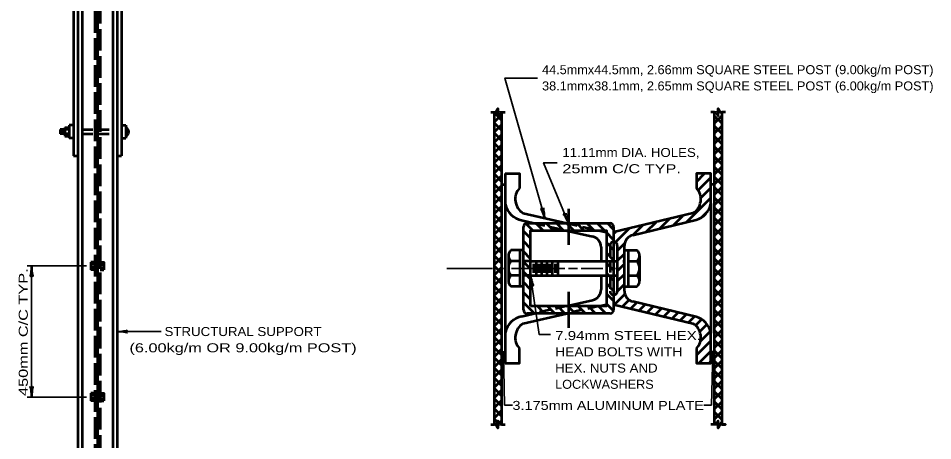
# Model space of a CAD drawing. Extents: x -96 to 759, y -450 to 94.
# Drawn here: x 216.3 to 520.4, y -261.3 to -120.9 of the extents above; entities that cross this region are included whole.
import ezdxf
from ezdxf.enums import TextEntityAlignment as Align

# ---------------------------------------------------------------- set-up
doc = ezdxf.new("R2010")
doc.units = 0
doc.header["$LTSCALE"] = 1.2
doc.linetypes.add('LONG_DASHED', pattern=[7.5, 6, -1.5])
doc.linetypes.add('MEDIUM_DASHED', pattern=[4.5, 3, -1.5])
doc.layers.add('1', color=7, linetype='Continuous', lineweight=53)

msp = doc.modelspace()

# ---------------------------------------------------------------- linework, layer by layer
at = {"layer": '1'}
for p, q in [((237.567, -31.518), (237.567, -274.002)), ((242.649, -31.518), (242.649, -266.742)), ((234.663, -34.422), (234.663, -166.554)), ((236.115, -34.422), (236.115, -274.002)), ((247.731, -34.422), (247.731, -274.002)), ((249.183, -34.422), (249.183, -274.002)), ((250.635, -34.422), (250.635, -166.554)), ((449.028, -151.1), (449.096, -151.032)), ((449.311, -151.461), (449.028, -151.179)), ((373.428, -152.096), (374.628, -152.096)), ((377.028, -154.717), (374.628, -152.317)), ((374.628, -155.254), (377.028, -152.854)), ((377.028, -152.096), (378.228, -152.096)), ((447.828, -152.096), (446.628, -152.096)), ((447.828, -152.3), (448.032, -152.096)), ((447.828, -155.694), (450.228, -153.294)), ((450.228, -155.773), (447.828, -153.373)), ((450.228, -152.379), (449.945, -152.096)), ((451.428, -152.096), (450.228, -152.096)), ((233.211, -157.842), (230.307, -157.842)), ((230.307, -157.842), (230.307, -159.294)), ((231.759, -157.116), (231.759, -160.02)), ((231.759, -157.116), (233.211, -157.116)), ((234.663, -156.39), (233.211, -156.39)), ((233.211, -156.39), (233.211, -160.746)), ((250.635, -156.39), (252.087, -156.39)), ((252.087, -156.39), (252.087, -160.746)), ((377.028, -158.111), (374.628, -155.711)), ((374.628, -158.648), (377.028, -156.248)), ((447.828, -159.088), (450.228, -156.688)), ((450.228, -159.167), (447.828, -156.767)), ((233.211, -159.294), (230.307, -159.294)), ((231.033, -158.205), (231.033, -158.931)), ((231.759, -160.02), (233.211, -160.02)), ((234.663, -160.746), (233.211, -160.746)), ((250.635, -160.746), (252.087, -160.746)), ((377.028, -161.505), (374.628, -159.105)), ((374.628, -162.042), (377.028, -159.642)), ((447.828, -162.482), (450.228, -160.082)), ((450.228, -162.561), (447.828, -160.161)), ((377.028, -164.899), (374.628, -162.499)), ((374.628, -165.436), (377.028, -163.036)), ((447.828, -165.876), (450.228, -163.476)), ((450.228, -165.955), (447.828, -163.555)), ((234.663, -166.554), (236.115, -166.554)), ((249.183, -166.554), (250.635, -166.554)), ((377.028, -168.293), (374.628, -165.894)), ((374.628, -168.83), (377.028, -166.43)), ((447.828, -169.27), (450.228, -166.871)), ((450.228, -169.349), (447.828, -166.949)), ((377.028, -171.688), (374.628, -169.288)), ((374.628, -172.224), (377.028, -169.824)), ((377.028, -175.082), (374.628, -172.682)), ((374.628, -175.619), (377.028, -173.219)), ((378.228, -172.496), (378.228, -235.496)), ((441.828, -175.188), (444.52, -172.496)), ((447.828, -172.665), (450.228, -170.265)), ((450.228, -172.743), (447.828, -170.343)), ((377.028, -178.476), (374.628, -176.076)), ((377.028, -176.096), (378.228, -176.096)), ((442.385, -178.025), (446.628, -173.782)), ((447.828, -176.096), (446.628, -176.096)), ((447.828, -176.059), (450.228, -173.659)), ((450.228, -176.137), (447.828, -173.737)), ((374.628, -179.013), (377.028, -176.613)), ((443.239, -180.565), (446.628, -177.176)), ((447.828, -179.453), (450.228, -177.053)), ((450.228, -179.532), (447.828, -177.132)), ((377.028, -181.87), (374.628, -179.47)), ((374.628, -182.407), (377.028, -180.007)), ((438.535, -188.663), (446.628, -180.57)), ((447.828, -182.847), (450.228, -180.447)), ((450.228, -182.926), (447.828, -180.526)), ((377.028, -185.264), (374.628, -182.864)), ((374.628, -185.801), (377.028, -183.401)), ((399.296, -184.184), (399.296, -196.184)), ((399.296, -184.184), (399.296, -196.184)), ((443.512, -187.08), (445.634, -184.958)), ((446.628, -182.454), (446.628, -225.537)), ((447.828, -186.241), (450.228, -183.841)), ((450.228, -186.32), (447.828, -183.92)), ((377.028, -188.658), (374.628, -186.258)), ((374.628, -189.195), (377.028, -186.795)), ((383.696, -188.036), (387.866, -188.984)), ((384.228, -185.696), (398.696, -188.984)), ((420.66, -192.932), (441.707, -187.906)), ((429.617, -190.793), (432.858, -187.551)), ((434.076, -189.728), (437.317, -186.486)), ((447.828, -189.635), (450.228, -187.235)), ((450.228, -189.714), (447.828, -187.314)), ((377.028, -192.052), (374.628, -189.652)), ((374.628, -192.589), (377.028, -190.189)), ((384.296, -217.808), (384.296, -190.184)), ((387.454, -191.384), (385.124, -189.053)), ((385.496, -188.984), (413.096, -188.984)), ((390.848, -191.384), (388.448, -188.984)), ((394.243, -191.384), (391.843, -188.984)), ((397.637, -191.384), (395.237, -188.984)), ((398.426, -191.384), (407.294, -193.399)), ((401.031, -191.384), (398.631, -188.984)), ((404.425, -191.384), (402.025, -188.984)), ((407.819, -191.384), (405.419, -188.984)), ((411.213, -191.384), (408.813, -188.984)), ((409.256, -191.384), (411.896, -191.984)), ((414.296, -191.073), (412.207, -188.984)), ((414.296, -190.184), (414.296, -191.984)), ((414.902, -195.325), (419.482, -190.746)), ((420.699, -192.922), (423.941, -189.681)), ((425.158, -191.858), (428.399, -188.616)), ((447.828, -193.029), (450.228, -190.629)), ((450.228, -193.108), (447.828, -190.708)), ((377.028, -195.446), (374.628, -193.046)), ((374.628, -195.983), (377.028, -193.583)), ((386.696, -194.02), (384.296, -191.62)), ((414.296, -194.467), (411.896, -192.067)), ((414.296, -192.537), (415.023, -191.81)), ((447.828, -196.423), (450.228, -194.023)), ((450.228, -196.502), (447.828, -194.102)), ((377.028, -198.841), (374.628, -196.441)), ((374.628, -199.377), (377.028, -196.977)), ((386.696, -197.414), (384.296, -195.014)), ((410.096, -196.91), (410.096, -201.596)), ((414.296, -197.861), (411.896, -195.461)), ((414.296, -195.134), (414.296, -212.858)), ((415.496, -198.126), (417.989, -195.633)), ((415.496, -196.433), (415.496, -211.558)), ((417.896, -211.558), (417.896, -196.433)), ((447.828, -199.817), (450.228, -197.418)), ((450.228, -199.896), (447.828, -197.496)), ((377.028, -202.235), (374.628, -199.835)), ((374.628, -202.771), (377.028, -200.371)), ((379.288, -199.802), (379.288, -208.189)), ((384.296, -197.996), (380.096, -197.996)), ((383.096, -197.996), (383.096, -209.996)), ((386.696, -200.808), (384.296, -198.408)), ((414.296, -201.255), (411.896, -198.855)), ((415.496, -201.52), (417.896, -199.12)), ((417.896, -197.996), (422.096, -197.996)), ((419.096, -197.996), (419.096, -209.996)), ((422.903, -199.802), (422.903, -208.189)), ((240.471, -201.947), (240.471, -204.488)), ((241.742, -201.947), (240.471, -201.947)), ((377.028, -205.629), (374.628, -203.229)), ((383.096, -201.596), (380.096, -201.596)), ((386.696, -204.202), (384.296, -201.802)), ((386.696, -201.596), (411.896, -201.596)), ((387.596, -202.496), (387.596, -205.496)), ((388.496, -201.596), (388.496, -206.396)), ((389.396, -202.496), (389.396, -205.496)), ((390.296, -201.596), (390.296, -206.396)), ((391.196, -202.496), (391.196, -205.496)), ((392.096, -201.596), (392.096, -206.396)), ((392.996, -202.496), (392.996, -205.496)), ((393.896, -201.596), (393.896, -206.396)), ((394.796, -202.496), (394.796, -205.496)), ((395.696, -201.596), (395.696, -206.396)), ((414.296, -204.649), (411.896, -202.249)), ((415.496, -204.914), (417.896, -202.514)), ((419.096, -201.596), (422.096, -201.596)), ((447.828, -203.212), (450.228, -200.812)), ((450.228, -203.29), (447.828, -200.89)), ((241.742, -204.488), (240.471, -204.488)), ((243.557, -204.488), (244.827, -204.488)), ((374.628, -206.166), (377.028, -203.766)), ((377.028, -209.023), (374.628, -206.623)), ((383.096, -206.396), (380.096, -206.396)), ((386.696, -207.596), (384.296, -205.196)), ((386.696, -206.396), (411.896, -206.396)), ((410.096, -206.396), (410.096, -211.082)), ((414.296, -208.043), (411.896, -205.643)), ((415.496, -208.308), (417.896, -205.908)), ((419.096, -206.396), (422.096, -206.396)), ((447.828, -206.606), (450.228, -204.206)), ((450.228, -206.684), (447.828, -204.284)), ((374.628, -209.56), (377.028, -207.16)), ((386.696, -210.99), (384.296, -208.59)), ((414.296, -211.437), (411.896, -209.037)), ((415.475, -211.723), (417.896, -209.302)), ((447.828, -210), (450.228, -207.6)), ((450.228, -210.079), (447.828, -207.679)), ((377.028, -212.417), (374.628, -210.017)), ((374.628, -212.954), (377.028, -210.554)), ((384.296, -209.996), (380.096, -209.996)), ((386.696, -214.384), (384.296, -211.984)), ((399.296, -211.808), (399.296, -223.808)), ((399.296, -211.808), (399.296, -223.808)), ((414.296, -214.831), (411.896, -212.431)), ((414.529, -216.063), (418.055, -212.536)), ((417.896, -209.996), (422.096, -209.996)), ((447.828, -213.394), (450.228, -210.994)), ((450.228, -213.473), (447.828, -211.073)), ((377.028, -215.811), (374.628, -213.411)), ((374.628, -216.348), (377.028, -213.948)), ((387.925, -219.008), (384.296, -215.378)), ((398.427, -216.608), (407.294, -214.592)), ((414.225, -218.155), (411.896, -215.826)), ((414.296, -212.902), (414.341, -212.856)), ((417.269, -216.718), (419.476, -214.51)), ((420.008, -217.372), (422, -215.38)), ((441.707, -220.086), (420.66, -215.06)), ((447.828, -216.788), (450.228, -214.388)), ((450.228, -216.867), (447.828, -214.467)), ((377.028, -219.205), (374.628, -216.805)), ((374.628, -219.742), (377.028, -217.342)), ((391.319, -219.008), (388.919, -216.608)), ((394.713, -219.008), (392.313, -216.608)), ((398.107, -219.008), (395.707, -216.608)), ((401.502, -219.008), (399.102, -216.608)), ((404.896, -219.008), (402.496, -216.608)), ((408.29, -219.008), (405.89, -216.608)), ((409.256, -216.608), (411.896, -216.008)), ((411.684, -219.008), (409.284, -216.608)), ((414.296, -216.008), (414.296, -217.808)), ((422.748, -218.026), (424.74, -216.034)), ((425.488, -218.68), (427.48, -216.689)), ((428.228, -219.335), (430.22, -217.343)), ((430.968, -219.989), (432.96, -217.997)), ((433.707, -220.643), (435.699, -218.651)), ((447.828, -220.182), (450.228, -217.782)), ((450.228, -220.261), (447.828, -217.861)), ((377.028, -222.599), (374.628, -220.199)), ((374.628, -223.136), (377.028, -220.736)), ((383.696, -219.955), (387.866, -219.008)), ((384.228, -222.296), (398.696, -219.008)), ((413.096, -219.008), (385.496, -219.008)), ((436.447, -221.298), (438.439, -219.306)), ((439.187, -221.952), (441.179, -219.96)), ((441.538, -222.995), (443.587, -220.946)), ((447.828, -223.576), (450.228, -221.176)), ((450.228, -223.655), (447.828, -221.255)), ((377.028, -225.993), (374.628, -223.593)), ((374.628, -226.53), (377.028, -224.13)), ((442.895, -225.032), (445.337, -222.59)), ((443.123, -228.198), (446.453, -224.869)), ((447.828, -226.97), (450.228, -224.57)), ((450.228, -227.049), (447.828, -224.649)), ((377.028, -229.388), (374.628, -226.988)), ((374.628, -229.924), (377.028, -227.524)), ((447.828, -230.365), (450.228, -227.965)), ((377.028, -232.782), (374.628, -230.382)), ((374.628, -233.318), (377.028, -230.918)), ((441.828, -232.888), (446.628, -228.088)), ((450.228, -230.443), (447.828, -228.043)), ((377.028, -236.176), (374.628, -233.776)), ((377.028, -231.896), (378.228, -231.896)), ((442.614, -235.496), (446.628, -231.482)), ((447.828, -231.896), (446.628, -231.896)), ((447.828, -233.759), (450.228, -231.359)), ((450.228, -233.837), (447.828, -231.437)), ((374.628, -236.713), (377.028, -234.312)), ((446.008, -235.496), (446.628, -234.876)), ((447.828, -237.153), (450.228, -234.753)), ((450.228, -237.231), (447.828, -234.831)), ((377.028, -239.57), (374.628, -237.17)), ((374.628, -240.107), (377.028, -237.707)), ((447.828, -240.547), (450.228, -238.147)), ((450.228, -240.626), (447.828, -238.226)), ((377.028, -242.964), (374.628, -240.564)), ((374.628, -243.501), (377.028, -241.101)), ((447.828, -243.941), (450.228, -241.541)), ((450.228, -244.02), (447.828, -241.62)), ((240.471, -245.507), (240.471, -248.048)), ((241.742, -245.507), (240.471, -245.507)), ((377.028, -246.358), (374.628, -243.958)), ((374.628, -246.895), (377.028, -244.495)), ((447.828, -247.335), (450.228, -244.935)), ((450.228, -247.414), (447.828, -245.014)), ((241.742, -248.048), (240.471, -248.048)), ((243.557, -248.048), (244.827, -248.048)), ((377.028, -249.752), (374.628, -247.352)), ((374.628, -250.289), (377.028, -247.889)), ((447.828, -250.729), (450.228, -248.329)), ((450.228, -250.808), (447.828, -248.408)), ((377.028, -253.146), (374.628, -250.746)), ((374.628, -253.683), (377.028, -251.283)), ((447.828, -254.123), (450.228, -251.723)), ((450.228, -254.202), (447.828, -251.802)), ((375.828, -255.34), (374.628, -254.14)), ((376.221, -255.483), (377.028, -254.677)), ((448.527, -255.896), (447.828, -255.196)), ((449.449, -255.896), (450.228, -255.117)), ((373.428, -255.896), (374.628, -255.896)), ((375.422, -256.283), (375.828, -255.877)), ((377.028, -255.896), (378.228, -255.896)), ((447.828, -255.896), (446.628, -255.896))]:
    msp.add_line(p, q, dxfattribs=at)
at = {"layer": '1', "linetype": 'LONG_DASHED'}
for p, q in [((243.557, -34.422), (243.557, -274.002)), ((241.742, -55.476), (241.742, -268.711))]:
    msp.add_line(p, q, dxfattribs=at)
at = {"layer": '1', "linetype": 'MEDIUM_DASHED'}
for p, q in [((237.567, -157.842), (247.731, -157.842)), ((237.567, -159.294), (247.731, -159.294)), ((387.866, -188.984), (398.426, -191.384)), ((398.696, -188.984), (409.256, -191.384)), ((413.096, -196.433), (413.096, -211.558)), ((241.742, -202.673), (240.471, -202.673)), ((241.742, -202.673), (243.557, -202.673)), ((241.742, -202.673), (243.557, -202.673)), ((243.557, -202.673), (244.827, -202.673)), ((386.696, -201.596), (384.296, -201.596)), ((411.896, -201.596), (417.896, -201.596)), ((241.742, -203.762), (240.471, -203.762)), ((241.742, -203.762), (243.557, -203.762)), ((243.557, -203.762), (244.827, -203.762)), ((386.696, -206.396), (384.296, -206.396)), ((411.896, -206.396), (417.896, -206.396)), ((398.427, -216.608), (387.866, -219.008)), ((409.256, -216.608), (398.696, -219.008)), ((241.742, -246.233), (240.471, -246.233)), ((241.742, -246.233), (243.557, -246.233)), ((243.557, -246.233), (244.827, -246.233)), ((241.742, -247.322), (240.471, -247.322)), ((241.742, -247.322), (243.557, -247.322)), ((243.557, -247.322), (244.827, -247.322))]:
    msp.add_line(p, q, dxfattribs=at)
at = {"layer": '1', "lineweight": 35}
for p, q in [((239.019, -203.217), (219.325, -203.217)), ((220.777, -203.217), (220.777, -246.777)), ((358.82, -203.996), (374.028, -203.996)), ((376.428, -203.996), (377.628, -203.996)), ((380.381, -203.996), (398.096, -203.996)), ((399.296, -203.996), (402.296, -203.996)), ((403.496, -203.996), (410.696, -203.996)), ((414.852, -203.996), (416.638, -203.996)), ((249.183, -224.997), (263.792, -224.997)), ((377.628, -231.896), (378.017, -249.469)), ((447.228, -231.896), (446.838, -249.469)), ((239.019, -246.777), (219.325, -246.777)), ((378.017, -249.469), (380.69, -249.469)), ((444.255, -249.469), (446.838, -249.469))]:
    msp.add_line(p, q, dxfattribs=at)
for points in [[(391.462, -187.34), (378.122, -140.76), (389, -140.76)], [(399.296, -188.984), (391.015, -168.872), (395.528, -168.872)], [(386.696, -206.396), (389.547, -226.01), (393.256, -226.01)]]:
    msp.add_lwpolyline(points, dxfattribs=at)
at = {"layer": '1'}
for points in [[(374.628, -255.896), (374.628, -152.096), (375.228, -152.096), (375.828, -150.896), (375.828, -153.296), (376.428, -152.096), (377.028, -152.096), (377.028, -255.896), (376.428, -255.896), (375.828, -254.696), (375.828, -257.096), (375.228, -255.896)], [(447.828, -255.896), (447.828, -152.096), (448.428, -152.096), (449.028, -153.296), (449.028, -150.896), (449.628, -152.096), (450.228, -152.096), (450.228, -255.896), (451.428, -255.896)], [(447.828, -255.896), (447.828, -152.096), (448.428, -152.096), (449.028, -153.296), (449.028, -150.896), (449.628, -152.096), (450.228, -152.096), (450.228, -255.896), (449.628, -255.896), (449.028, -257.096), (449.028, -254.696), (448.428, -255.896)], [(386.696, -216.608), (386.696, -191.384), (411.896, -191.384), (411.896, -216.608)]]:
    msp.add_lwpolyline(points, close=True, dxfattribs=at)
for points in [[(378.228, -172.496), (383.028, -172.496), (383.028, -177.296)], [(446.628, -182.454), (446.628, -172.496), (441.828, -172.496), (441.828, -177.296)], [(440.628, -185.696), (414.296, -191.984), (414.296, -195.134)], [(243.557, -201.947), (244.827, -201.947), (244.827, -204.488)], [(414.296, -212.858), (414.296, -216.008), (440.628, -222.296)], [(441.828, -230.696), (441.828, -235.496), (446.628, -235.496), (446.628, -225.537)], [(378.228, -235.496), (383.028, -235.496), (383.028, -230.696)], [(243.557, -245.507), (244.827, -245.507), (244.827, -248.048)]]:
    msp.add_lwpolyline(points, dxfattribs=at)
for centre, radius, start, end in [((251.52, -158.568), 1.559, 291.34576, 68.65425), ((387.043, -181.008), 5.468, 137.24693, 239.01328), ((437.812, -181.008), 5.468, 300.98672, 42.75307), ((385.021, -181.268), 6.896, 192.24961, 258.91782), ((439.834, -181.268), 6.896, 285.76159, 350.09896), ((385.496, -190.184), 1.2, 90, 180), ((413.096, -190.184), 1.2, 0, 90), ((406.496, -196.91), 3.6, 0, 77.19552), ((421.496, -196.433), 3.6, 103.43049, 180), ((414.285, -196.347), 1.213, 355.93658, 88.42125), ((381.699, -199.796), 2.41, 131.68177, 180.15453), ((381.699, -199.809), 2.41, 179.84547, 228.31823), ((381.699, -199.796), 2.41, 180.15453, 228.31823), ((420.493, -199.796), 2.41, 359.84547, 48.31823), ((420.493, -199.796), 2.41, 311.68177, 359.84548), ((420.493, -199.809), 2.41, 311.68177, 0.15452), ((383.259, -203.996), 3.971, 142.81241, 217.18759), ((383.259, -203.996), 3.971, 142.81241, 217.18759), ((418.932, -203.996), 3.971, 322.81241, 37.18759), ((418.932, -203.996), 3.971, 322.81241, 37.18759), ((381.699, -208.183), 2.41, 131.68177, 180.15453), ((381.699, -208.196), 2.41, 131.68177, 179.84548), ((420.493, -208.183), 2.41, 359.84547, 48.31823), ((420.493, -208.196), 2.41, 0.15452, 48.31823), ((381.699, -208.196), 2.41, 179.84547, 228.31823), ((420.493, -208.196), 2.41, 311.68177, 0.15452), ((406.496, -211.082), 3.6, 282.80434, 0), ((414.285, -211.644), 1.213, 271.57875, 4.06342), ((421.496, -211.558), 3.6, 180, 256.56931), ((385.496, -217.808), 1.2, 180, 270), ((413.096, -217.808), 1.2, 270, 0), ((385.021, -226.723), 6.896, 101.08218, 167.75039), ((439.834, -226.723), 6.896, 9.90104, 74.23791), ((387.043, -226.984), 5.468, 120.98672, 222.75307), ((437.812, -226.984), 5.468, 317.24693, 59.01328)]:
    msp.add_arc(centre, radius, start, end, dxfattribs=at)
at = {"layer": '1', "linetype": 'MEDIUM_DASHED'}
for centre, start, end in [((414.306, -196.347), 91.57875, 184.06342), ((414.306, -211.644), 175.93658, 268.42125)]:
    msp.add_arc(centre, 1.213, start, end, dxfattribs=at)
at = {"layer": '1', "lineweight": 40}
for centre, major_axis, ratio, start_param, end_param in [((390.783, -186.172), (0.77, -2.008), 0.122415, 0.8963533, 3.1415927), ((391.336, -185.977), (0.378, -2.084), 0.07063, 3.1407148, 5.41811), ((398.491, -187.899), (0.989, -1.91), 0.122415, 0.8963533, 3.1415927), ((399.019, -187.644), (0.608, -2.029), 0.07063, 3.1407148, 5.41811), ((220.523, -204.562), (0.211, 2.108), 0.07063, 3.1407148, 5.41811), ((220.523, -204.562), (0.211, 2.108), 0.07063, 3.1407148, 5.41811), ((221.109, -204.527), (-0.187, 2.143), 0.122415, 0.8963533, 3.1415927), ((221.109, -204.527), (-0.187, 2.143), 0.122415, 0.8963533, 3.1415927), ((386.638, -207.763), (-0.095, 2.116), 0.07063, 3.1407148, 5.41811), ((387.212, -207.644), (-0.494, 2.094), 0.122415, 0.8963533, 3.1415927), ((250.493, -224.666), (-2.143, -0.187), 0.122415, 0.8963533, 3.1415927), ((250.528, -225.251), (-2.108, 0.211), 0.07063, 3.1407148, 5.41811), ((377.404, -233.246), (0.164, 2.112), 0.07063, 3.1407148, 5.41811), ((377.988, -233.198), (-0.235, 2.138), 0.122415, 0.8963533, 3.1415927), ((446.944, -233.234), (0.257, 2.103), 0.07063, 3.1407148, 5.41811), ((447.53, -233.212), (-0.14, 2.146), 0.122415, 0.8963533, 3.1415927), ((220.446, -245.468), (0.187, -2.143), 0.122415, 0.8963533, 3.1415927), ((220.446, -245.468), (0.187, -2.143), 0.122415, 0.8963533, 3.1415927), ((221.031, -245.433), (-0.211, -2.108), 0.07063, 3.1407148, 5.41811), ((221.031, -245.433), (-0.211, -2.108), 0.07063, 3.1407148, 5.41811)]:
    msp.add_ellipse(centre, major_axis=major_axis, ratio=ratio, start_param=start_param, end_param=end_param, dxfattribs=at)

# ---------------------------------------------------------------- texts
at = {"layer": '1'}
for s, width, p in [('44.5mmx44.5mm, 2.66mm SQUARE STEEL POST (9.00kg/m POST)', 1.05, (390.491, -139.448)), ('38.1mmx38.1mm, 2.65mm SQUARE STEEL POST (6.00kg/m POST)', 1.05, (390.491, -144.848)), ('11.11mm DIA. HOLES,', 1.1, (397.23, -166.975)), ('25mm C/C TYP.', 1.35, (397.23, -172.375)), ('7.94mm STEEL HEX.', 1.25, (394.837, -227.85)), ('HEAD BOLTS WITH', 1.15, (394.837, -233.25)), ('HEX. NUTS AND', 1.1, (394.837, -238.65)), ('LOCKWASHERS', 1.05, (394.837, -244.05))]:
    msp.add_text(s, height=3, dxfattribs=dict(at, width=width)).set_placement(p)
at = {"layer": '1', "width": 1.35}
msp.add_text('450mm C/C TYP.', height=3, rotation=90, dxfattribs=at).set_placement((219.497, -225.214), align=Align.CENTER)
at = {"layer": '1'}
for s, width, p in [('STRUCTURAL SUPPORT', 1.1, (291.068, -226.511)), ('(6.00kg/m OR 9.00kg/m POST)', 1.35, (291.068, -231.911)), ('3.175mm ALUMINUM PLATE', 1.2, (412.475, -251.074))]:
    msp.add_text(s, height=3, dxfattribs=dict(at, width=width)).set_placement(p, align=Align.CENTER)

doc.saveas('drawing.dxf')
